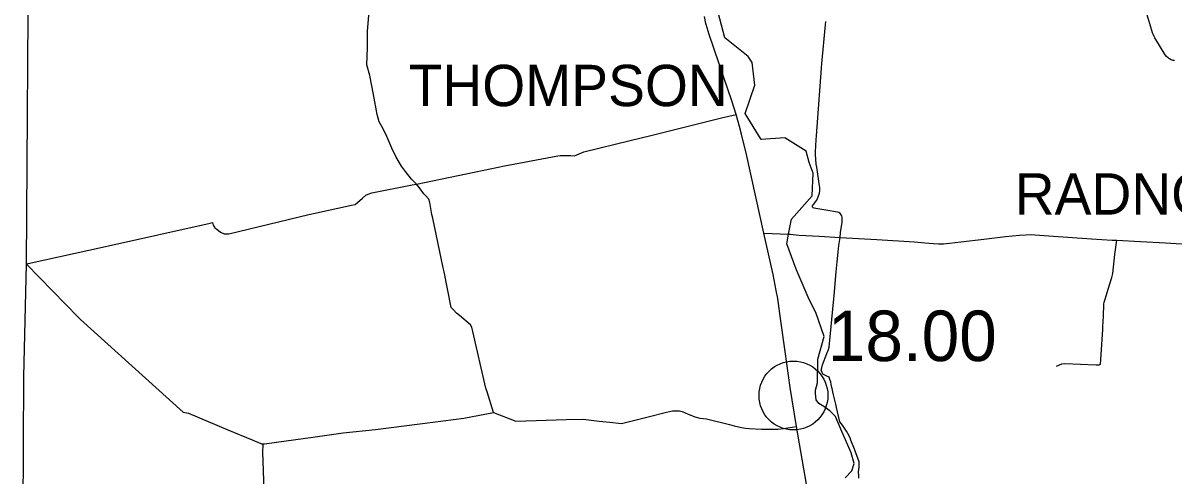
# Model space of a CAD drawing. Extents: x 1597222 to 1925846, y 496284 to 911751.
# Drawn here: x 1759615 to 1784691, y 863780 to 873644 of the extents above; entities that cross this region are included whole.
import ezdxf

# ---------------------------------------------------------------- set-up
doc = ezdxf.new("R2010")
doc.units = 0
for name, color, linetype in [('Default', 7, 'Continuous'), ('GM_X_County', 7, 'Continuous'), ('GM_X_County_Road', 7, 'Continuous'), ('GM_X_State_Route', 7, 'Continuous'), ('GM_X_Township', 7, 'Continuous'), ('GM_X_Township_Road', 7, 'Continuous'), ('GM_X_Township_Text', 7, 'Continuous')]:
    doc.layers.add(name, color=color, linetype=linetype)

msp = doc.modelspace()

# ---------------------------------------------------------------- linework, layer by layer
at = {"layer": 'Default'}
msp.add_circle((1776400, 865532), 750, dxfattribs=at)
at = {"layer": 'GM_X_County'}
msp.add_lwpolyline([(1759615, 862978), (1759631, 865937), (1759690, 868390), (1759745, 876009), (1759795, 878524), (1759881, 881868), (1759886, 882027), (1760071, 889009), (1760084, 889480), (1760161, 891042), (1765804, 890577), (1771666, 890080), (1775269, 889747), (1775894, 889674), (1776032, 889658), (1778209, 889456), (1784657, 889014), (1789933, 888711), (1791146, 888682), (1797651, 888237), (1803655, 887971)], dxfattribs=at)
at = {"layer": 'GM_X_County_Road'}
for points in [[(1775757, 869068), (1776296, 869048), (1776328, 869045)], [(1776328, 869045), (1776526, 869023), (1776962, 868999), (1777415, 868976), (1778218, 868930), (1779038, 868876), (1779266, 868856), (1779449, 868845), (1779563, 868837), (1779670, 868838), (1779800, 868851), (1780050, 868882), (1780545, 868937), (1781023, 868994), (1781326, 869024), (1781460, 869035), (1781558, 869036), (1781964, 869008), (1782895, 868945), (1783343, 868918), (1783443, 868912), (1783964, 868885), (1784505, 868858), (1785211, 868814)]]:
    msp.add_lwpolyline(points, dxfattribs=at)
at = {"layer": 'GM_X_State_Route'}
for points in [[(1776749, 863221), (1776467, 864856), (1776332, 865707), (1776223, 866494), (1776116, 867210), (1776059, 867642), (1776027, 867820), (1775960, 868164), (1775757, 869068), (1775581, 869857), (1775376, 870780), (1775268, 871225), (1775225, 871389), (1775149, 871651), (1775057, 871948), (1774882, 872459), (1774774, 872777), (1774561, 873391), (1774496, 873614), (1774491, 873632), (1774460, 873783)], [(1784699, 872825), (1784673, 872831), (1784633, 872843), (1784596, 872861), (1784578, 872873), (1784561, 872885), (1784531, 872913), (1784502, 872951), (1784275, 873322), (1784260, 873348), (1784235, 873404), (1784225, 873433), (1784211, 873480), (1784162, 873624), (1784100, 873843)]]:
    msp.add_lwpolyline(points, dxfattribs=at)
at = {"layer": 'GM_X_Township'}
msp.add_lwpolyline([(1777527, 863741), (1777673, 863892), (1777723, 864054), (1777660, 864284), (1777430, 864796), (1777319, 865072), (1777194, 865201), (1777060, 865295), (1776951, 865360), (1776896, 865440), (1776878, 865579), (1776878, 865651), (1776924, 865805), (1776935, 866323), (1777068, 866814), (1776889, 867340), (1776741, 867625), (1776460, 868285), (1776256, 868836), (1776296, 869048), (1776358, 869376), (1776809, 869882), (1776827, 870373), (1776746, 870605), (1776679, 870853), (1776212, 871143), (1775698, 871106), (1775350, 871674), (1775561, 872294), (1775504, 872788), (1775414, 872915), (1774908, 873319), (1774761, 873873)], dxfattribs=at)
at = {"layer": 'GM_X_Township_Road'}
for points in [[(1768190, 870136), (1768081, 870244), (1767947, 870409), (1767861, 870528), (1767742, 870726), (1767651, 870916), (1767543, 871171), (1767459, 871342), (1767376, 871496), (1767334, 871653), (1767253, 872089), (1767171, 872502), (1767108, 872731), (1767120, 873106), (1767121, 873461), (1767150, 873817), (1767171, 874681), (1767185, 875170), (1767198, 875395), (1767211, 875858), (1767213, 876255), (1767271, 876519)], [(1777415, 868976), (1777428, 869079), (1777461, 869308), (1777465, 869392), (1777460, 869417), (1777454, 869442), (1777439, 869470), (1777418, 869496), (1777389, 869516), (1777362, 869525), (1777107, 869568), (1776890, 869605), (1776854, 869611), (1776831, 869616), (1776818, 869633), (1776815, 869649), (1776815, 869660), (1776839, 869695), (1776908, 869790), (1776942, 869860), (1776971, 869938), (1776977, 869994), (1776978, 870056), (1776964, 870147), (1776911, 870505), (1776899, 870572), (1776883, 870783), (1776879, 870838), (1776899, 871102), (1776905, 871187), (1777011, 872662), (1777019, 872766), (1777098, 873608), (1777104, 873680)], [(1759690, 868390), (1759727, 868410), (1761412, 868777), (1761477, 868792), (1763692, 869289), (1763746, 869301), (1763760, 869243), (1763792, 869185), (1763834, 869153), (1763918, 869091), (1763998, 869055), (1764099, 869051), (1765844, 869474), (1765945, 869498), (1766771, 869677), (1766852, 869694), (1767012, 869832), (1767086, 869895), (1767134, 869916), (1767211, 869949), (1768093, 870117), (1768190, 870136), (1770000, 870510), (1770072, 870525), (1771265, 870752), (1771318, 870762), (1771500, 870762), (1771553, 870757), (1771628, 870750), (1771831, 870839), (1772843, 871089), (1773290, 871196), (1774104, 871397), (1774834, 871578), (1775149, 871651)], [(1769863, 865161), (1769724, 865615), (1769699, 865695), (1769412, 866929), (1769391, 867020), (1769367, 867072), (1769122, 867272), (1769056, 867326), (1768985, 867405), (1768944, 867450), (1768787, 868227), (1768770, 868312), (1768540, 869397), (1768524, 869474), (1768475, 869734), (1768460, 869811), (1768385, 869886), (1768344, 869927), (1768250, 870055), (1768190, 870136)], [(1777238, 865704), (1777225, 865769), (1777214, 865830), (1777195, 865879), (1777176, 865933), (1777128, 865955), (1777042, 865995), (1777008, 866087), (1777021, 866138), (1777036, 866199), (1777129, 866446), (1777162, 866534), (1777180, 866584), (1777280, 867635), (1777287, 867710), (1777333, 868225), (1777354, 868440), (1777374, 868656), (1777389, 868796), (1777415, 868976)], [(1782133, 866169), (1782246, 866221), (1782316, 866230), (1782999, 866203), (1783063, 866198), (1783088, 866215), (1783098, 866319), (1783138, 866969), (1783144, 867025), (1783155, 867257), (1783164, 867523), (1783171, 867568), (1783190, 867631), (1783256, 867847), (1783339, 868104), (1783356, 868188), (1783405, 868604), (1783443, 868912)], [(1759690, 868390), (1760823, 867233), (1760868, 867188), (1763103, 865172), (1763217, 865148), (1764080, 864786), (1764607, 864567), (1764793, 864488), (1764809, 864483), (1764838, 864478), (1764837, 864452)], [(1777823, 863735), (1777822, 863788), (1777819, 863869), (1777829, 863974), (1777835, 864032), (1777835, 864085), (1777760, 864282), (1777729, 864364), (1777653, 864561), (1777633, 864611), (1777585, 864705), (1777559, 864756), (1777467, 864885), (1777411, 864962), (1777339, 865271), (1777322, 865342), (1777272, 865548), (1777256, 865613), (1777242, 865686), (1777238, 865704)], [(1764838, 864478), (1764876, 864478), (1765089, 864511), (1765980, 864631), (1766593, 864719), (1767293, 864790), (1768540, 864950), (1769216, 865042), (1769863, 865161), (1770355, 864971), (1771015, 864995), (1771451, 865009), (1771818, 865018), (1772164, 864974), (1772400, 864954), (1772652, 864922), (1773233, 865070), (1773636, 865166), (1773765, 865195), (1773819, 865202), (1773867, 865200), (1773915, 865196), (1773975, 865182), (1774108, 865128), (1774162, 865106), (1774201, 865086), (1774253, 865069), (1774360, 865042), (1774506, 865023), (1775005, 864899), (1775107, 864873), (1775271, 864835), (1775313, 864827), (1775354, 864820), (1775437, 864811), (1775701, 864802), (1775944, 864798), (1776020, 864798), (1776062, 864800), (1776185, 864815), (1776467, 864856)], [(1764837, 864452), (1764833, 864303), (1764859, 863478), (1764860, 863401), (1764913, 862293), (1764917, 862205)]]:
    msp.add_lwpolyline(points, dxfattribs=at)

# ---------------------------------------------------------------- texts
at = {"layer": 'Default'}
msp.add_text('18.00', height=1100, dxfattribs=at).set_placement((1777150, 866282))
at = {"layer": 'GM_X_Township_Text'}
for s, p in [('THOMPSON', (1768016, 871834)), ('RADNOR', (1781221, 869472))]:
    msp.add_text(s, height=900, rotation=0, dxfattribs=at).set_placement(p)

doc.saveas('drawing.dxf')
